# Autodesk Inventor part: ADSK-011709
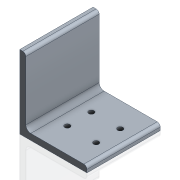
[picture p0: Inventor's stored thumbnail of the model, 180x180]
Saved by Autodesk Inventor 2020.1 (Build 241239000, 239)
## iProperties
Created: 2000-03
Part Number: ADSK-011709
Material: Pearson Aluminium
Document SubType Name: Modeling
Designer: cmcgourin
Density: 2.71 g/cm^3
Appearance: Pearson-Aluminum
Mass: 181.802 g
Surface Area: 239.096 cm^2
Volume: 67.0855 cm^3
Control State: 0
Master: False
Checked Out: False
Shininess: 35.0
Length Units: 11269
Angle Units: 11279
Time Units: 11290
Mass Units: 11283
Length Display Precision: 3
Angle Display Precision: 2
Compacted: True
Cutlength: 23.25
Material Desc: Material Description goes here
Material_Number: Pearson
Dimensions: 69,9x76,2x76,2 mm
Mass: 0,182 kg
DocNumber: ADSK-011709.ipt
Folder: 01 - Themengebiete\Simplification\01 - Packaging machine\
VDS_Category: 3D Komponenten
Density: 2.71
Volumn: 76.96821696269427
Area: 263.9546157505454
PropertySet Name: Model Information
Author: cmcgourin
Revision Number: -
Title: profile
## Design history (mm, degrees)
node "Extrusion1" dims "d9" = 0, "Length" = 76.2
sketch "Skizze3"
  geometry: L1 (12.42, -25.6)-(42.42, -25.6); L2 (42.42, -25.6)-(42.42, -50.6); L3 (42.42, -50.6)-(12.42, -50.6); L4 (12.42, -50.6)-(12.42, -25.6); L5 (58.42, 0)-(58.42, -76.2) reference; 7 further points
  constraints: 8 end point, 4 coincident, 2 midpoint, 2 parallel, 1 horizontal, 1 horizontal alignment, 1 perpendicular
  dimensions: "d10" = 30 distance of L1.start L1.end; "d11" = 25 distance of L3.end L1.start; "d12" = 16 distance between parallel lines of L5 L2
hole "Bohrung1" sketch "Skizze3" at (12.42, -25.6), (42.42, -25.6), (42.42, -50.6), (12.42, -50.6) diameter "d13" = 5.5; stored, may be unused: countersink angle "d17" = 90 deg, drill point angle "d19" = 118 deg; dims "d14" = 16, "d15" = 10.4, "d16" = 2, "d18" = 8
node "Solide1"
node "Corps solides"
node "Corps surfaciques"
sketch "Sketch2"
  geometry: L1 (32.408, 38.758)-(102.258, 38.758); L2 (32.408, 114.958)-(32.408, 38.758); L3 (38.758, 111.783)-(38.758, 50.188); L4 (43.838, 45.108)-(99.083, 45.108); L5 (32.408, 114.958)-(35.583, 114.958); L6 (102.258, 41.933)-(102.258, 38.758); A1 r 3.175 centre (35.583, 111.783) between (38.758, 111.783) and (35.583, 114.958); A2 r 3.175 centre (99.083, 41.933) between (102.258, 41.933) and (99.083, 45.108); A3 r 5.08 centre (43.838, 50.188) between (38.758, 50.188) and (43.838, 45.108); 1 further point
  constraints: 12 end point, 6 point on circle, 6 tangent, 3 centre point, 1 coincident, 1 equal radius, 1 horizontal, 1 perpendicular, 1 other
  dimensions: "d0" = 6.35 distance between parallel lines of L2 L3 (= Thickness); "d6" = 3.175 radius of A1 (= 0.5 x Thickness); "d7" = 5.08 radius of A3 (computed from Thickness); "d2" = 76.2 distance between parallel lines of L1 L5; "d4" = 69.85 distance between parallel lines of L6 L2
other parameters: "Thickness" = 6.35, "Vertical_Length" = 63.5, "Horizontal_length" = 38.1
